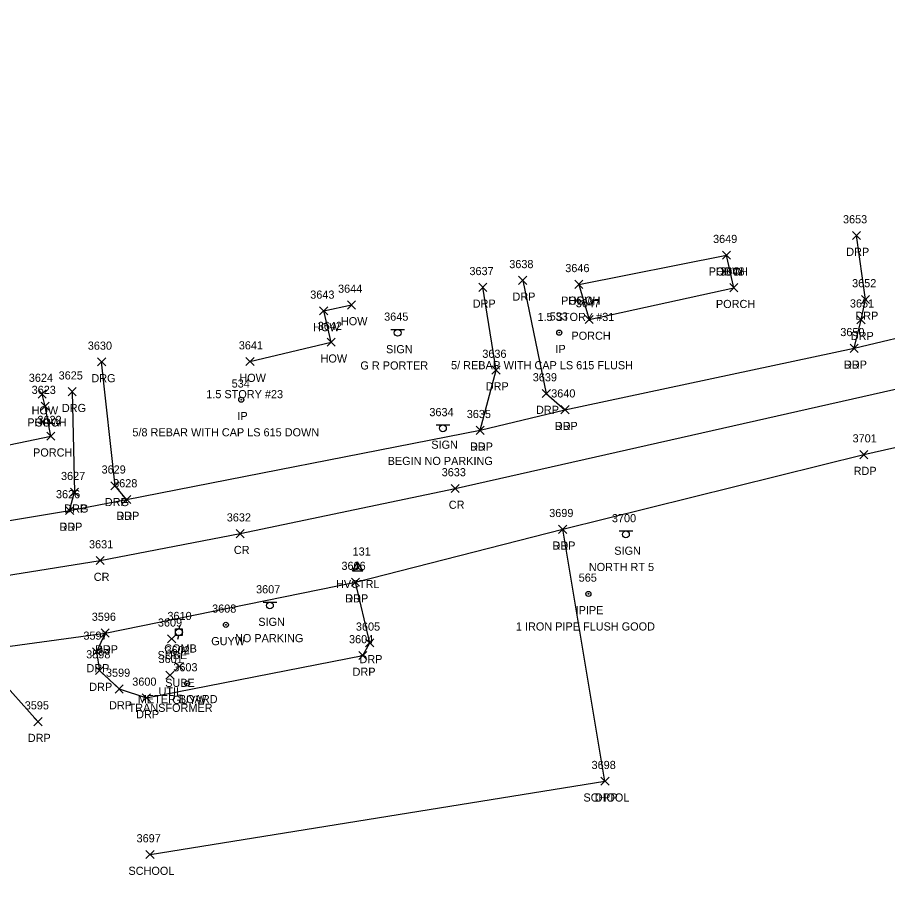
# Model space of a CAD drawing. Extents: x 1690689 to 1696275, y 438760 to 444007.
# Drawn here: x 1691458.4 to 1691672.4, y 442358.8 to 442572.4 of the extents above; entities that cross this region are included whole.
import ezdxf

# ---------------------------------------------------------------- set-up
doc = ezdxf.new("R2010")
doc.units = 0
for name, color, linetype in [('C_A', 7, 'Continuous'), ('C_I', 7, 'Continuous'), ('CPSM', 7, 'Continuous'), ('L_A', 7, 'Continuous'), ('L_C', 7, 'Continuous'), ('L_I', 7, 'Continuous'), ('L_TIC', 7, 'Continuous'), ('LBC', 7, 'Continuous'), ('LBF', 7, 'Continuous'), ('M_A', 7, 'Continuous'), ('M_C', 7, 'Continuous'), ('M_I', 7, 'Continuous'), ('MPIP', 7, 'Continuous'), ('MPIR', 7, 'Continuous'), ('P_A', 7, 'Continuous'), ('P_I', 7, 'Continuous'), ('P_TIC', 7, 'Continuous'), ('PET', 7, 'Continuous'), ('PRC', 7, 'Continuous'), ('R_A', 7, 'Continuous'), ('R_I', 7, 'Continuous'), ('R_TIC', 7, 'Continuous'), ('RDG', 7, 'Continuous'), ('RDP', 7, 'Continuous'), ('S_A', 7, 'Continuous'), ('S_C', 7, 'Continuous'), ('S_I', 7, 'Continuous'), ('SSGN', 7, 'Continuous'), ('U_A', 7, 'Continuous'), ('U_C', 7, 'Continuous'), ('U_I', 7, 'Continuous'), ('U_TIC', 7, 'Continuous'), ('UDEFAULT', 7, 'Continuous'), ('UP', 7, 'Continuous'), ('UPGW', 7, 'Continuous')]:
    doc.layers.add(name, color=color, linetype=linetype)

msp = doc.modelspace()

# ---------------------------------------------------------------- linework, layer by layer
at = {"layer": 'CPSM'}
for p, q in [((1691540.82, 442436.39), (1691542.07, 442438.56)), ((1691543.32, 442436.39), (1691542.07, 442438.56)), ((1691542.07, 442437.11), (1691542.07, 442438.56)), ((1691540.82, 442436.39), (1691542.07, 442437.11)), ((1691540.82, 442436.39), (1691543.32, 442436.39)), ((1691542.07, 442437.11), (1691542.07, 442437.11)), ((1691542.07, 442437.11), (1691543.32, 442436.39))]:
    msp.add_line(p, q, dxfattribs=at)
at = {"layer": 'L_TIC'}
for points in [[(1691631.78, 442512.93), (1691633.78, 442514.93)], [(1691633.78, 442512.93), (1691631.78, 442514.93)], [(1691631.78, 442512.93), (1691633.78, 442514.93)], [(1691633.78, 442512.93), (1691631.78, 442514.93)], [(1691595.49, 442505.76), (1691597.49, 442507.76)], [(1691597.49, 442505.76), (1691595.49, 442507.76)], [(1691595.49, 442505.76), (1691597.49, 442507.76)], [(1691597.49, 442505.76), (1691595.49, 442507.76)], [(1691633.56, 442504.94), (1691635.56, 442506.94)], [(1691635.56, 442504.94), (1691633.56, 442506.94)], [(1691539.57, 442500.7), (1691541.57, 442502.7)], [(1691541.57, 442500.7), (1691539.57, 442502.7)], [(1691532.73, 442499.24), (1691534.73, 442501.24)], [(1691534.73, 442499.24), (1691532.73, 442501.24)], [(1691598.03, 442497.14), (1691600.03, 442499.14)], [(1691600.03, 442497.14), (1691598.03, 442499.14)], [(1691534.57, 442491.55), (1691536.57, 442493.55)], [(1691536.57, 442491.55), (1691534.57, 442493.55)], [(1691514.6, 442486.78), (1691516.6, 442488.78)], [(1691516.6, 442486.78), (1691514.6, 442488.78)], [(1691463.53, 442478.8), (1691465.53, 442480.8)], [(1691465.53, 442478.8), (1691463.53, 442480.8)], [(1691464.23, 442475.83), (1691466.23, 442477.83)], [(1691466.23, 442475.83), (1691464.23, 442477.83)], [(1691464.23, 442475.83), (1691466.23, 442477.83)], [(1691466.23, 442475.83), (1691464.23, 442477.83)], [(1691465.65, 442468.45), (1691467.65, 442470.45)], [(1691467.65, 442468.45), (1691465.65, 442470.45)], [(1691601.9, 442383.65), (1691603.9, 442385.65)], [(1691603.9, 442383.65), (1691601.9, 442385.65)], [(1691490.03, 442365.63), (1691492.03, 442367.63)], [(1691492.03, 442365.63), (1691490.03, 442367.63)]]:
    msp.add_lwpolyline(points, dxfattribs=at)
at = {"layer": 'LBC'}
for points in [[(1691596.49, 442506.76), (1691632.78, 442513.93)], [(1691515.6, 442487.78), (1691535.57, 442492.55), (1691533.73, 442500.24), (1691540.57, 442501.7)], [(1691465.23, 442476.83), (1691464.53, 442479.8)], [(1691491.03, 442366.63), (1691602.9, 442384.65)]]:
    msp.add_lwpolyline(points, dxfattribs=at)
at = {"layer": 'LBF'}
for points in [[(1691596.49, 442506.76), (1691599.03, 442498.14), (1691634.56, 442505.94), (1691632.78, 442513.93)], [(1691421.78, 442462.21), (1691424.09, 442460.34), (1691445.26, 442464.94), (1691450.41, 442466.12), (1691466.65, 442469.45), (1691465.23, 442476.83)]]:
    msp.add_lwpolyline(points, dxfattribs=at)
at = {"layer": 'MPIP'}
for radius in [0.625, 0.0833]:
    msp.add_circle((1691598.83, 442430.69), radius, dxfattribs=at)
at = {"layer": 'MPIR'}
for centre, radius in [((1691591.66, 442494.89), 0.625), ((1691591.66, 442494.89), 0.0833), ((1691513.47, 442478.4), 0.625), ((1691513.47, 442478.4), 0.0833)]:
    msp.add_circle(centre, radius, dxfattribs=at)
at = {"layer": 'P_TIC'}
for points in [[(1691663.16, 442490.04), (1691665.16, 442492.04)], [(1691665.16, 442490.04), (1691663.16, 442492.04)], [(1691592.06, 442474.96), (1691594.06, 442476.96)], [(1691594.06, 442474.96), (1691592.06, 442476.96)], [(1691571.21, 442469.9), (1691573.21, 442471.9)], [(1691573.21, 442469.9), (1691571.21, 442471.9)], [(1691665.55, 442463.92), (1691667.55, 442465.92)], [(1691667.55, 442463.92), (1691665.55, 442465.92)], [(1691565.06, 442455.6), (1691567.06, 442457.6)], [(1691567.06, 442455.6), (1691565.06, 442457.6)], [(1691484.27, 442452.88), (1691486.27, 442454.88)], [(1691486.27, 442452.88), (1691484.27, 442454.88)], [(1691470.26, 442450.19), (1691472.26, 442452.19)], [(1691472.26, 442450.19), (1691470.26, 442452.19)], [(1691591.5, 442445.57), (1691593.5, 442447.57)], [(1691593.5, 442445.57), (1691591.5, 442447.57)], [(1691512.2, 442444.49), (1691514.2, 442446.49)], [(1691514.2, 442444.49), (1691512.2, 442446.49)], [(1691477.76, 442437.88), (1691479.76, 442439.88)], [(1691479.76, 442437.88), (1691477.76, 442439.88)], [(1691540.54, 442432.59), (1691542.54, 442434.59)], [(1691542.54, 442432.59), (1691540.54, 442434.59)], [(1691479.01, 442420.07), (1691481.01, 442422.07)], [(1691481.01, 442420.07), (1691479.01, 442422.07)]]:
    msp.add_lwpolyline(points, dxfattribs=at)
at = {"layer": 'PET'}
for points in [[(1691244.99, 442422.42), (1691274.8, 442426.79), (1691288.71, 442428.52), (1691321.88, 442431.22), (1691333.08, 442431.36), (1691372.74, 442436.52), (1691410.43, 442441.3), (1691430.74, 442444.46), (1691471.26, 442451.19), (1691485.27, 442453.88), (1691572.21, 442470.9), (1691593.06, 442475.96), (1691664.16, 442491.04), (1691682.81, 442495.5), (1691724.04, 442504.48), (1691768.38, 442514.48), (1691786.16, 442518.76), (1691792.23, 442520.23), (1691811.17, 442524.66), (1691956.19, 442557.56), (1691977.69, 442562.36), (1692021.28, 442572.37)], [(1691262.71, 442389.79), (1691278.62, 442392.36), (1691323.95, 442400.43), (1691413.56, 442412.73), (1691416.45, 442413.87), (1691418.24, 442414.27), (1691431.74, 442416.27), (1691440.51, 442417.83), (1691444.91, 442417.31), (1691446.93, 442416.56), (1691480.01, 442421.07), (1691541.54, 442433.59), (1691592.5, 442446.57), (1691666.55, 442464.92), (1691770.02, 442488.32), (1691794.27, 442493.8), (1691844.9, 442505.22), (1691966.82, 442532.71), (1692001.23, 442540.45), (1692024.42, 442545.45)]]:
    msp.add_lwpolyline(points, dxfattribs=at)
at = {"layer": 'PRC'}
msp.add_lwpolyline([(1691130.81, 442358.75), (1691152.44, 442373.63), (1691178.23, 442388.18), (1691209.8, 442400.63), (1691248.04, 442408.48), (1691275.24, 442412.28), (1691309.15, 442415.93), (1691347.17, 442419.98), (1691395.19, 442425.91), (1691433.65, 442431.72), (1691478.76, 442438.88), (1691513.2, 442445.49), (1691566.06, 442456.6), (1691813.76, 442512.5), (1691980.06, 442550.02), (1692039.61, 442563.23)], dxfattribs=at)
at = {"layer": 'R_TIC'}
for points in [[(1691663.73, 442517.76), (1691665.73, 442519.76)], [(1691665.73, 442517.76), (1691663.73, 442519.76)], [(1691571.88, 442505.03), (1691573.88, 442507.03)], [(1691573.88, 442505.03), (1691571.88, 442507.03)], [(1691581.66, 442506.74), (1691583.66, 442508.74)], [(1691583.66, 442506.74), (1691581.66, 442508.74)], [(1691665.97, 442502.05), (1691667.97, 442504.05)], [(1691667.97, 442502.05), (1691665.97, 442504.05)], [(1691664.86, 442497.07), (1691666.86, 442499.07)], [(1691666.86, 442497.07), (1691664.86, 442499.07)], [(1691663.16, 442490.04), (1691665.16, 442492.04)], [(1691665.16, 442490.04), (1691663.16, 442492.04)], [(1691478.13, 442486.7), (1691480.13, 442488.7)], [(1691480.13, 442486.7), (1691478.13, 442488.7)], [(1691575.1, 442484.7), (1691577.1, 442486.7)], [(1691577.1, 442484.7), (1691575.1, 442486.7)], [(1691470.86, 442479.38), (1691472.86, 442481.38)], [(1691472.86, 442479.38), (1691470.86, 442481.38)], [(1691587.46, 442478.93), (1691589.46, 442480.93)], [(1691589.46, 442478.93), (1691587.46, 442480.93)], [(1691592.06, 442474.96), (1691594.06, 442476.96)], [(1691594.06, 442474.96), (1691592.06, 442476.96)], [(1691571.21, 442469.9), (1691573.21, 442471.9)], [(1691573.21, 442469.9), (1691571.21, 442471.9)], [(1691481.42, 442456.26), (1691483.42, 442458.26)], [(1691483.42, 442456.26), (1691481.42, 442458.26)], [(1691481.42, 442456.26), (1691483.42, 442458.26)], [(1691483.42, 442456.26), (1691481.42, 442458.26)], [(1691471.44, 442454.67), (1691473.44, 442456.67)], [(1691473.44, 442454.67), (1691471.44, 442456.67)], [(1691471.44, 442454.67), (1691473.44, 442456.67)], [(1691473.44, 442454.67), (1691471.44, 442456.67)], [(1691484.27, 442452.88), (1691486.27, 442454.88)], [(1691486.27, 442452.88), (1691484.27, 442454.88)], [(1691470.26, 442450.19), (1691472.26, 442452.19)], [(1691472.26, 442450.19), (1691470.26, 442452.19)], [(1691591.5, 442445.57), (1691593.5, 442447.57)], [(1691593.5, 442445.57), (1691591.5, 442447.57)], [(1691540.54, 442432.59), (1691542.54, 442434.59)], [(1691542.54, 442432.59), (1691540.54, 442434.59)], [(1691479.01, 442420.07), (1691481.01, 442422.07)], [(1691481.01, 442420.07), (1691479.01, 442422.07)], [(1691544.04, 442417.66), (1691546.04, 442419.66)], [(1691546.04, 442417.66), (1691544.04, 442419.66)], [(1691476.9, 442415.43), (1691478.9, 442417.43)], [(1691478.9, 442415.43), (1691476.9, 442417.43)], [(1691542.35, 442414.55), (1691544.35, 442416.55)], [(1691544.35, 442414.55), (1691542.35, 442416.55)], [(1691477.59, 442410.84), (1691479.59, 442412.84)], [(1691479.59, 442410.84), (1691477.59, 442412.84)], [(1691482.46, 442406.32), (1691484.46, 442408.32)], [(1691484.46, 442406.32), (1691482.46, 442408.32)], [(1691489.13, 442404.12), (1691491.13, 442406.12)], [(1691491.13, 442404.12), (1691489.13, 442406.12)], [(1691462.48, 442398.3), (1691464.48, 442400.3)], [(1691464.48, 442398.3), (1691462.48, 442400.3)], [(1691601.9, 442383.65), (1691603.9, 442385.65)], [(1691603.9, 442383.65), (1691601.9, 442385.65)]]:
    msp.add_lwpolyline(points, dxfattribs=at)
at = {"layer": 'RDG'}
for points in [[(1691482.42, 442457.26), (1691479.13, 442487.7)], [(1691471.86, 442480.38), (1691472.44, 442455.67)]]:
    msp.add_lwpolyline(points, dxfattribs=at)
at = {"layer": 'RDP'}
for points in [[(1691664.16, 442491.04), (1691665.86, 442498.07), (1691666.97, 442503.05), (1691664.73, 442518.76)], [(1691582.66, 442507.74), (1691588.46, 442479.93), (1691593.06, 442475.96)], [(1691572.21, 442470.9), (1691576.1, 442485.7), (1691572.88, 442506.03)], [(1691471.26, 442451.19), (1691472.44, 442455.67)], [(1691485.27, 442453.88), (1691482.42, 442457.26)], [(1691602.9, 442384.65), (1691592.5, 442446.57)], [(1691480.01, 442421.07), (1691477.9, 442416.43), (1691478.59, 442411.84), (1691483.46, 442407.32), (1691490.13, 442405.12), (1691543.35, 442415.55), (1691545.04, 442418.66), (1691541.54, 442433.59)], [(1691446.93, 442416.56), (1691448.76, 442415.4), (1691451.03, 442413.1), (1691463.48, 442399.3)]]:
    msp.add_lwpolyline(points, dxfattribs=at)
at = {"layer": 'SSGN'}
for p, q in [((1691550.28, 442495.68), (1691553.61, 442495.68)), ((1691551.92, 442494.85), (1691551.92, 442494.85)), ((1691561.4, 442472.22), (1691564.73, 442472.22)), ((1691563.05, 442471.38), (1691563.05, 442471.38)), ((1691606.4, 442446.15), (1691609.73, 442446.15)), ((1691608.04, 442445.32), (1691608.04, 442445.32)), ((1691518.86, 442428.67), (1691522.19, 442428.67)), ((1691520.51, 442427.84), (1691520.51, 442427.84))]:
    msp.add_line(p, q, dxfattribs=at)
for centre in [(1691551.92, 442494.85), (1691563.05, 442471.38), (1691608.04, 442445.32), (1691520.51, 442427.84)]:
    msp.add_circle(centre, 0.833, dxfattribs=at)
at = {"layer": 'U_TIC'}
for points in [[(1691495.35, 442418.65), (1691497.35, 442420.65)], [(1691497.35, 442418.65), (1691495.35, 442420.65)], [(1691497.22, 442411.83), (1691499.22, 442413.83)], [(1691499.22, 442411.83), (1691497.22, 442413.83)]]:
    msp.add_lwpolyline(points, dxfattribs=at)
at = {"layer": 'UDEFAULT'}
for points in [[(1691494.95, 442409.69), (1691496.95, 442411.69)], [(1691496.95, 442409.69), (1691494.95, 442411.69)]]:
    msp.add_lwpolyline(points, dxfattribs=at)
at = {"layer": 'UP'}
for p, q in [((1691497.31, 442420.44), (1691497.31, 442422.1)), ((1691497.31, 442422.1), (1691498.97, 442422.1)), ((1691498.39, 442422.94), (1691498.14, 442422.1)), ((1691498.14, 442421.27), (1691498.14, 442421.27)), ((1691498.97, 442422.1), (1691498.97, 442420.44)), ((1691498.97, 442420.44), (1691497.31, 442420.44)), ((1691497.89, 442419.6), (1691498.14, 442420.44))]:
    msp.add_line(p, q, dxfattribs=at)
msp.add_circle((1691498.14, 442421.27), 0.833, dxfattribs=at)
at = {"layer": 'UPGW'}
for centre, radius in [((1691509.68, 442423.08), 0.625), ((1691509.68, 442423.08), 0.0833), ((1691500.13, 442408.66), 0.625), ((1691500.13, 442408.66), 0.0833)]:
    msp.add_circle(centre, radius, dxfattribs=at)

# ---------------------------------------------------------------- texts
at = {"layer": 'C_A'}
msp.add_text('HVCTRL', height=2, dxfattribs=at).set_placement((1691536.76, 442432.11))
at = {"layer": 'C_I'}
msp.add_text('131', height=2, dxfattribs=at).set_placement((1691540.84, 442440.11))
at = {"layer": 'L_A'}
for s, p in [('PORCH', (1691628.41, 442508.93)), ('HOW', (1691630.17, 442508.93)), ('PORCH', (1691592.11, 442501.76)), ('HOW', (1691593.87, 442501.76)), ('PORCH', (1691630.18, 442500.94)), ('HOW', (1691537.96, 442496.7)), ('HOW', (1691531.12, 442495.24)), ('PORCH', (1691594.65, 442493.14)), ('HOW', (1691532.96, 442487.55)), ('HOW', (1691512.99, 442482.78)), ('HOW', (1691461.91, 442474.8)), ('PORCH', (1691460.85, 442471.83)), ('HOW', (1691462.61, 442471.83)), ('PORCH', (1691462.27, 442464.45)), ('SCHOOL', (1691597.6, 442379.65)), ('SCHOOL', (1691485.72, 442361.63))]:
    msp.add_text(s, height=2, dxfattribs=at).set_placement(p)
at = {"layer": 'L_C'}
for s, p in [('1.5 STORY #31', (1691586.31, 442497.76)), ('1.5 STORY #23', (1691504.86, 442478.78))]:
    msp.add_text(s, height=2, dxfattribs=at).set_placement(p)
at = {"layer": 'L_I'}
for s, p in [('3649', (1691629.47, 442516.93)), ('3649', (1691629.47, 442516.93)), ('3646', (1691593.13, 442509.76)), ('3646', (1691593.13, 442509.76)), ('3648', (1691631.25, 442508.94)), ('3644', (1691537.26, 442504.7)), ('3643', (1691530.42, 442503.24)), ('3647', (1691595.72, 442501.14)), ('3642', (1691532.27, 442495.55)), ('3641', (1691512.86, 442490.78)), ('3624', (1691461.22, 442482.8)), ('3623', (1691461.92, 442479.83)), ('3623', (1691461.92, 442479.83)), ('3622', (1691463.34, 442472.45)), ('3698', (1691599.6, 442387.65)), ('3697', (1691487.72, 442369.63))]:
    msp.add_text(s, height=2, dxfattribs=at).set_placement(p)
at = {"layer": 'M_A'}
for s, p in [('IP', (1691590.71, 442489.89)), ('IP', (1691512.51, 442473.4)), ('IPIPE', (1691595.67, 442425.69))]:
    msp.add_text(s, height=2, dxfattribs=at).set_placement(p)
at = {"layer": 'M_C'}
for s, p in [('5/ REBAR WITH CAP LS 615 FLUSH', (1691565.05, 442485.89)), ('5/8 REBAR WITH CAP LS 615 DOWN', (1691486.69, 442469.4)), ('1 IRON PIPE FLUSH GOOD', (1691581, 442421.69))]:
    msp.add_text(s, height=2, dxfattribs=at).set_placement(p)
at = {"layer": 'M_I'}
for s, p in [('533', (1691589.3, 442497.89)), ('534', (1691511.1, 442481.4)), ('565', (1691596.43, 442433.69))]:
    msp.add_text(s, height=2, dxfattribs=at).set_placement(p)
at = {"layer": 'P_A'}
for s, p in [('RDP', (1691661.65, 442486.04)), ('RDP', (1691590.55, 442470.96)), ('RDP', (1691569.7, 442465.9)), ('RDP', (1691664.04, 442459.92)), ('CR', (1691564.49, 442451.6)), ('RDP', (1691482.75, 442448.88)), ('RDP', (1691468.75, 442446.19)), ('CR', (1691511.64, 442440.49)), ('RDP', (1691589.99, 442441.57)), ('CR', (1691477.19, 442433.88)), ('RDP', (1691539.03, 442428.59)), ('RDP', (1691477.5, 442416.07))]:
    msp.add_text(s, height=2, dxfattribs=at).set_placement(p)
at = {"layer": 'P_I'}
for s, p in [('3650', (1691660.76, 442494.04)), ('3640', (1691589.67, 442478.96)), ('3635', (1691568.91, 442473.9)), ('3701', (1691663.78, 442467.92)), ('3633', (1691562.75, 442459.6)), ('3628', (1691481.96, 442456.88)), ('3626', (1691467.9, 442454.19)), ('3699', (1691589.18, 442449.57)), ('3632', (1691509.9, 442448.49)), ('3631', (1691476.02, 442441.88)), ('3606', (1691538.1, 442436.59)), ('3596', (1691476.7, 442424.07))]:
    msp.add_text(s, height=2, dxfattribs=at).set_placement(p)
at = {"layer": 'R_A'}
for s, p in [('DRP', (1691662.22, 442513.76)), ('DRP', (1691580.15, 442502.74)), ('DRP', (1691570.37, 442501.03)), ('DRP', (1691664.46, 442498.05)), ('DRP', (1691663.34, 442493.07)), ('DRP', (1691661.65, 442486.04)), ('DRG', (1691476.61, 442482.7)), ('DRP', (1691573.58, 442480.7)), ('DRG', (1691469.35, 442475.38)), ('DRP', (1691585.94, 442474.93)), ('DRP', (1691590.55, 442470.96)), ('DRP', (1691569.7, 442465.9)), ('DRG', (1691479.91, 442452.26)), ('DRP', (1691479.91, 442452.26)), ('DRG', (1691469.93, 442450.67)), ('DRP', (1691469.93, 442450.67)), ('DRP', (1691482.75, 442448.88)), ('DRP', (1691468.75, 442446.19)), ('DRP', (1691589.99, 442441.57)), ('DRP', (1691539.03, 442428.59)), ('DRP', (1691477.5, 442416.07)), ('DRP', (1691542.53, 442413.66)), ('DRP', (1691475.39, 442411.43)), ('DRP', (1691540.83, 442410.55)), ('DRP', (1691476.08, 442406.84)), ('DRP', (1691480.95, 442402.32)), ('DRP', (1691487.62, 442400.12)), ('DRP', (1691460.97, 442394.3)), ('DRP', (1691600.39, 442379.65))]:
    msp.add_text(s, height=2, dxfattribs=at).set_placement(p)
at = {"layer": 'R_I'}
for s, p in [('3653', (1691661.42, 442521.76)), ('3637', (1691569.57, 442509.03)), ('3638', (1691579.36, 442510.74)), ('3652', (1691663.66, 442506.05)), ('3651', (1691663.12, 442501.07)), ('3650', (1691660.76, 442494.04)), ('3630', (1691475.73, 442490.7)), ('3636', (1691572.73, 442488.7)), ('3625', (1691468.55, 442483.38)), ('3639', (1691585.14, 442482.93)), ('3640', (1691589.67, 442478.96)), ('3635', (1691568.91, 442473.9)), ('3629', (1691479.11, 442460.26)), ('3629', (1691479.11, 442460.26)), ('3627', (1691469.14, 442458.67)), ('3627', (1691469.14, 442458.67)), ('3628', (1691481.96, 442456.88)), ('3626', (1691467.9, 442454.19)), ('3699', (1691589.18, 442449.57)), ('3606', (1691538.1, 442436.59)), ('3596', (1691476.7, 442424.07)), ('3605', (1691541.65, 442421.66)), ('3597', (1691474.64, 442419.43)), ('3604', (1691539.96, 442418.55)), ('3598', (1691475.33, 442414.84)), ('3599', (1691480.19, 442410.32)), ('3600', (1691486.66, 442408.12)), ('3595', (1691460.22, 442402.3)), ('3698', (1691599.6, 442387.65))]:
    msp.add_text(s, height=2, dxfattribs=at).set_placement(p)
at = {"layer": 'S_A'}
for p in [(1691549.06, 442489.83), (1691560.19, 442466.36), (1691605.18, 442440.3), (1691517.65, 442422.82)]:
    msp.add_text('SIGN', height=2, dxfattribs=at).set_placement(p)
at = {"layer": 'S_C'}
for s, p in [('G R PORTER', (1691542.76, 442485.83)), ('BEGIN NO PARKING', (1691549.46, 442462.36)), ('NORTH RT 5', (1691598.92, 442436.3)), ('NO PARKING', (1691511.93, 442418.82))]:
    msp.add_text(s, height=2, dxfattribs=at).set_placement(p)
at = {"layer": 'S_I'}
for s, p in [('3645', (1691548.6, 442497.83)), ('3634', (1691559.72, 442474.36)), ('3700', (1691604.6, 442448.3)), ('3607', (1691517.1, 442430.82))]:
    msp.add_text(s, height=2, dxfattribs=at).set_placement(p)
at = {"layer": 'U_A'}
for s, p in [('GUYW', (1691506.07, 442418.08)), ('COMB', (1691494.52, 442416.27)), ('SUBE', (1691492.89, 442414.65)), ('SUBE', (1691494.76, 442407.83)), ('UTIL', (1691493.11, 442405.69)), ('GUYW', (1691496.53, 442403.66))]:
    msp.add_text(s, height=2, dxfattribs=at).set_placement(p)
at = {"layer": 'U_C'}
for s, p in [('METER BOARD', (1691488.02, 442403.83)), ('TRANSFORMER', (1691485.75, 442401.69))]:
    msp.add_text(s, height=2, dxfattribs=at).set_placement(p)
at = {"layer": 'U_I'}
for s, p in [('3608', (1691506.3, 442426.08)), ('3610', (1691495.31, 442424.27)), ('3609', (1691492.96, 442422.65)), ('3602', (1691494.84, 442415.83)), ('3601', (1691493.13, 442413.69)), ('3603', (1691496.75, 442411.66))]:
    msp.add_text(s, height=2, dxfattribs=at).set_placement(p)

doc.saveas('drawing.dxf')
